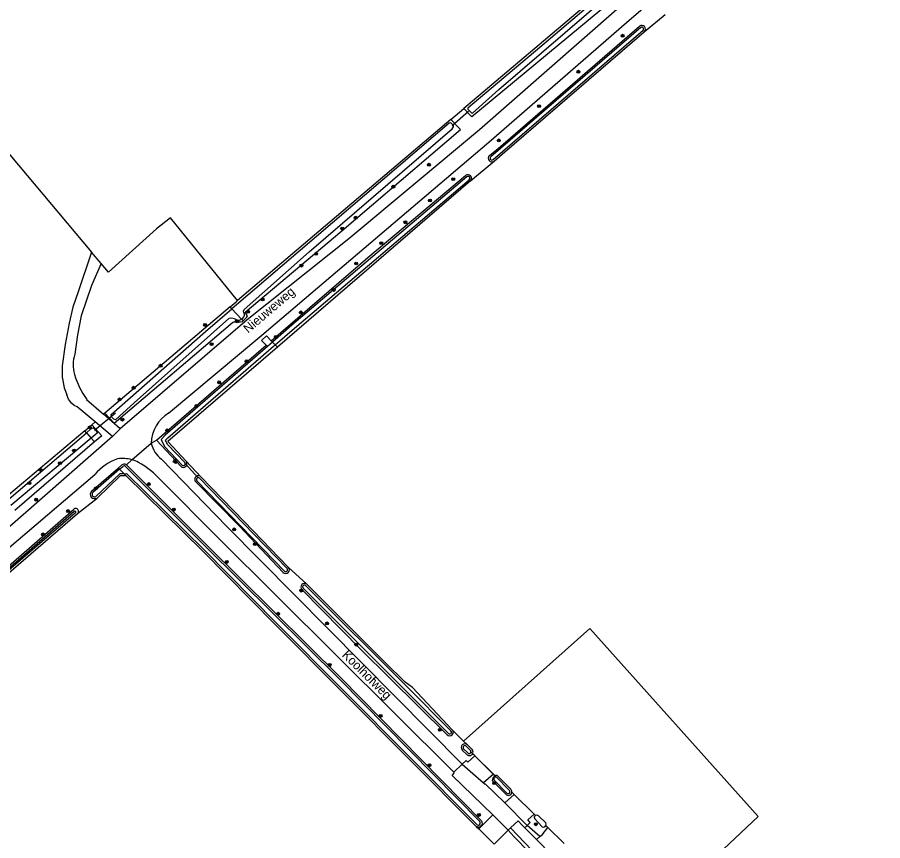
# Model space of a CAD drawing. Extents: x 141000 to 143000, y 400580 to 403500.
# Drawn here: x 142087.7 to 142326.5, y 403003.4 to 403230.8 of the extents above; entities that cross this region are included whole.
import ezdxf

# ---------------------------------------------------------------- set-up
doc = ezdxf.new("R2010")
doc.units = 0
for name, color, linetype in [('gg-anno-openbare ruimte label', 7, 'Continuous'), ('gg-knt-bronhoudergrens', 7, 'Continuous'), ('gg-knt-onverhard', 7, 'Continuous'), ('gg-knt-verharding', 7, 'Continuous'), ('gg-knt-verharding nz', 7, 'Continuous'), ('gg-kntw-bovenkant insteek waterloop', 7, 'Continuous'), ('gg-kntw-waterlijn', 7, 'Continuous'), ('gg-kwrk-duiker nz buis', 7, 'Continuous'), ('gt-grn-groengrens', 7, 'Continuous'), ('gt-grn-vlakafsluiter', 7, 'Continuous'), ('gt-grn-weggrens', 7, 'Continuous'), ('gt-symb-boom', 7, 'Continuous'), ('gt-symb-brandkraan', 7, 'Continuous'), ('gt-symb-waterafsluiter', 7, 'Continuous')]:
    doc.layers.add(name, color=color, linetype=linetype)

# ---------------------------------------------------------------- blocks, each defined once
blk = doc.blocks.new('gt0-BOOM')
at = {"layer": 'gt-symb-boom'}
for radius in [0.4, 0.2]:
    blk.add_circle((0, 0), radius, dxfattribs=at)
blk = doc.blocks.new('gt0-WAFSL')
at = {"layer": 'gt-symb-waterafsluiter'}
for p, q in [((-0.5, -0.33), (0, 0.67)), ((0, 0.67), (0.5, -0.33)), ((0.5, -0.33), (-0.5, -0.33))]:
    blk.add_line(p, q, dxfattribs=at)
blk = doc.blocks.new('gt0-BR')
at = {"layer": 'gt-symb-brandkraan'}
for centre, radius, start, end in [((-0.24, 0), 0.206, 107.5669, 252.4331), ((0.6, -2.66), 3, 106.892, 107.5669), ((0, -0.69), 0.938, 73.108, 106.892), ((-0.6, -2.66), 3, 72.4331, 73.108), ((0.24, 0), 0.206, 287.567, 72.4331), ((0.6, 2.66), 3, 252.4331, 253.108), ((0, 0.69), 0.938, 253.108, 286.8921), ((-0.6, 2.66), 3, 286.8921, 287.567)]:
    blk.add_arc(centre, radius, start, end, dxfattribs=at)

msp = doc.modelspace()

# ---------------------------------------------------------------- linework, layer by layer
at = {"layer": 'gg-knt-bronhoudergrens'}
for p, q in [((142260.7, 403226.8), (142266.52, 403231.53)), ((142207.31, 403202.55), (142210.95, 403205.59)), ((142212.74, 403185.58), (142219.29, 403191.07)), ((142138.33, 403103.86), (142134.23, 403108.17)), ((142104.32, 403093.73), (142109.68, 403098.03)), ((142167.55, 403074.21), (142162.46, 403078.9)), ((142207.71, 403034.05), (142210.84, 403030.92)), ((142210.84, 403030.92), (142211.88, 403029.88)), ((142214.35, 403007.34), (142215.06, 403006.63)), ((142215.06, 403006.63), (142219.28, 403002.43))]:
    msp.add_line(p, q, dxfattribs=at)
for points in [[(142018.46, 403199.94), (142054.28, 403230.01), (142108.17, 403165.95)], [(142148.46, 403152.56), (142129.93, 403175.44), (142126.09, 403172.32), (142112.85, 403160.38), (142110.82, 403162.8)], [(142210.84, 403030.92), (142245.72, 403061.99), (142292.19, 403010.09), (142261.85, 402981.56)]]:
    msp.add_lwpolyline(points, dxfattribs=at)
at = {"layer": 'gg-knt-onverhard'}
for p, q in [((142110.82, 403162.8), (142108.17, 403165.95)), ((142218.91, 403010.5), (142215.06, 403006.63)), ((142223.1, 403006.27), (142219.28, 403002.43))]:
    msp.add_line(p, q, dxfattribs=at)
for points in [[(142210.49, 403024.54), (142145.47, 403090.13), (142127.46, 403108.75)], [(142127.35, 403102.83), (142143.07, 403087.03), (142208.11, 403022.33)]]:
    msp.add_lwpolyline(points, dxfattribs=at)
for centre, radius, start, end in [((142132.29, 403114.98), 7.88, 193.4484, 232.2377), ((142116.75, 403099.86), 9.1, 61.3827, 73.9104), ((142110.3, 403087.98), 22.61, 41.0533, 61.4369)]:
    msp.add_arc(centre, radius, start, end, dxfattribs=at)
at = {"layer": 'gg-knt-verharding'}
for p, q in [((142116.02, 403117.12), (142113.94, 403114.98)), ((142208.11, 403022.33), (142210.49, 403024.54)), ((142219.09, 403021.77), (142216.3, 403019.41)), ((142222.18, 403013.9), (142224.78, 403016.19)), ((142231.92, 403004.57), (142228.4, 403007.62)), ((142223.78, 403006.91), (142229.69, 403000.79)), ((142230.98, 403003.74), (142227.74, 403006.96)), ((142235.23, 402999.43), (142230.98, 403003.74))]:
    msp.add_line(p, q, dxfattribs=at)
for points in [[(142129.43, 403121.45), (142155.13, 403142.95), (142217.83, 403196.26), (142255.83, 403229.33), (142298.44, 403265.98), (142313.46, 403277.45), (142353.81, 403312.2), (142392, 403344.92)], [(142362.71, 403326.12), (142350.92, 403316.23), (142295.63, 403269.59), (142253.14, 403232.93), (142215.27, 403199.68), (142179.13, 403169.58), (142151.11, 403147.23), (142116.02, 403117.12)], [(142113.94, 403114.98), (142069.01, 403075.7), (142040.23, 403051.3), (141996.37, 403014.63), (141979.56, 403000.04), (141957.73, 402981.47)], [(141914.25, 402939.09), (141985.78, 403000), (142000, 403012.42), (142042.58, 403048.33), (142071.63, 403072.64), (142109.08, 403104.56)], [(142210.49, 403024.54), (142211.58, 403025.55), (142212.04, 403025.1), (142213.94, 403026.8)], [(142218.91, 403010.5), (142207.69, 403021.43), (142208.23, 403022.04), (142208.04, 403022.27), (142208.11, 403022.33)], [(142216.3, 403019.41), (142216.78, 403019.01), (142216.84, 403019.08), (142222.18, 403013.9)], [(142223.1, 403006.27), (142222.3, 403007.12), (142218.91, 403010.5)], [(142228.4, 403007.62), (142229.21, 403008.44), (142228.56, 403009.14), (142230.36, 403010.72)], [(142223.78, 403006.91), (142225.94, 403008.92), (142226.93, 403007.77), (142227.74, 403006.96)], [(142229.05, 403000.17), (142224.8, 403004.45), (142223.1, 403006.27)], [(142231.92, 403004.57), (142232.49, 403005.02), (142234.12, 403007.04)]]:
    msp.add_lwpolyline(points, dxfattribs=at)
for centre, radius, start, end in [((142134.5, 403112.97), 9.88, 120.8938, 178.951), ((142119.97, 403095.36), 14.25, 108.9408, 139.789), ((142116.76, 403099.86), 9.09, 73.9261, 98.9757)]:
    msp.add_arc(centre, radius, start, end, dxfattribs=at)
at = {"layer": 'gg-knt-verharding nz'}
for p, q in [((142228.4, 403007.62), (142227.74, 403006.96)), ((142223.78, 403006.91), (142223.1, 403006.27)), ((142230.98, 403003.74), (142231.92, 403004.57))]:
    msp.add_line(p, q, dxfattribs=at)
at = {"layer": 'gg-kntw-bovenkant insteek waterloop'}
for p, q in [((142277.23, 403261.71), (142210.95, 403205.59)), ((142207.31, 403202.55), (142148.46, 403152.56)), ((142212.74, 403185.58), (142159.44, 403139.68)), ((142146.4, 403150.81), (142111.85, 403121.47)), ((142126.07, 403114.03), (142156.38, 403140.22)), ((142106.28, 403116.6), (142108.24, 403118.26)), ((142109.01, 403113.52), (142086.98, 403094.57)), ((142132.78, 403106.79), (142126.07, 403114.03)), ((142108.17, 403099.91), (142115.55, 403106.3)), ((142115.55, 403106.3), (142116.45, 403107.08)), ((142211.88, 403029.88), (142213.35, 403028.38)), ((142211.8, 403027.11), (142210.49, 403028.44)), ((142222.46, 403016.21), (142218.76, 403019.99)), ((142219.44, 403021.3), (142219.52, 403021.34)), ((142220.04, 403021.54), (142223.05, 403018.45)), ((142223.05, 403018.45), (142223.86, 403017.64)), ((142231.53, 403010.31), (142231.36, 403010.38)), ((142233.58, 403008.29), (142231.53, 403010.31)), ((142230.47, 403009.41), (142232.55, 403007.26))]:
    msp.add_line(p, q, dxfattribs=at)
for points in [[(142301.84, 403277.83), (142294.39, 403271.48), (142251.65, 403235.24), (142213.15, 403203.31), (142210.95, 403205.59)], [(142218, 403192.6), (142220.38, 403194.56), (142259.39, 403228.31)], [(142219.29, 403191.07), (142221.49, 403193), (142260.7, 403226.8)], [(142149.98, 403146.97), (142150.18, 403147.15), (142150.94, 403147.92), (142151.2, 403148.37), (142150.56, 403149.33), (142177.23, 403171.8), (142210, 403199.83), (142207.31, 403202.55)], [(142157.77, 403141.4), (142184.45, 403164.44), (142211.41, 403187.07)], [(142146.4, 403150.81), (142148.05, 403152.21), (142148.46, 403152.56)], [(142111.85, 403121.47), (142114.37, 403118.71), (142147.07, 403146.52), (142147.42, 403146.64), (142148.6, 403146.72), (142149.18, 403146.68), (142149.78, 403146.8), (142149.98, 403146.97)], [(142156.38, 403140.22), (142155.03, 403141.5), (142156.48, 403142.84), (142157.77, 403141.4)], [(142159.44, 403139.68), (142129.21, 403113.65), (142134.23, 403108.17)], [(142108.24, 403118.26), (142110.97, 403115.21), (142109.01, 403113.52)], [(142106.28, 403116.6), (142085.31, 403098.86), (142085.19, 403098.75), (142084.18, 403097.9)], [(142117.81, 403107.19), (142140.08, 403084.87), (142176.97, 403048.39), (142215.78, 403008.92), (142215.9, 403008.57), (142215.96, 403007.9), (142215.55, 403007.42), (142215.1, 403007.02), (142214.35, 403007.34)], [(142109.68, 403098.03), (142116.14, 403104.24), (142117.63, 403104.26)], [(142117.63, 403104.26), (142138.85, 403083.33), (142158.85, 403063.08), (142214.35, 403007.34)], [(142162.46, 403078.9), (142150.26, 403091.54), (142138.33, 403103.86)], [(142161.03, 403077.5), (142148.95, 403090.22), (142136.9, 403102.47)], [(142002.23, 403008.95), (142005.78, 403011.79), (142027.06, 403029.52), (142066.63, 403063.32), (142070.81, 403066.65), (142103.18, 403094.88)], [(142003.62, 403007.33), (142007.25, 403010.28), (142028.05, 403028.17), (142067.65, 403062.22), (142071.61, 403065.62), (142104.32, 403093.73)], [(142206.29, 403032.64), (142182.54, 403056.09), (142166.2, 403072.74)], [(142207.71, 403034.05), (142196.71, 403045.73), (142194.72, 403047.21), (142189.15, 403052.7), (142167.55, 403074.21)], [(142219.52, 403021.34), (142219.73, 403021.45), (142220.04, 403021.54)]]:
    msp.add_lwpolyline(points, dxfattribs=at)
for centre, radius, start, end in [((142260.05, 403227.55), 1, 310.8159, 130.7532), ((142218.65, 403191.84), 1, 130.7754, 309.2026), ((142212.05, 403186.31), 1, 313.6011, 130.318), ((142133.5, 403107.49), 1, 224.1342, 42.9884), ((142117.19, 403106.38), 1.02, 52.3409, 136.8669), ((142137.62, 403103.16), 1, 44.1479, 224.1504), ((142109.03, 403099.05), 1.21, 135.0902, 302.5414), ((142103.75, 403094.31), 0.809, 314.3724, 134.3761), ((142161.75, 403078.2), 1, 224.1503, 44.148), ((142166.91, 403073.45), 1, 49.6731, 225.1122), ((142207, 403033.35), 1, 224.8575, 44.7779), ((142211.19, 403029.16), 1, 46.1765, 226.1733), ((142212.44, 403027.91), 1.03, 231.0576, 330.3978), ((142212.43, 403027.91), 1.03, 330.6858, 27.2033), ((142220.29, 403020.03), 1.52, 123.6435, 181.6306), ((142223.16, 403016.93), 0.998, 352.8578, 45.6064), ((142223.16, 403016.92), 1, 225.5504, 352.9573), ((142231.02, 403009.8), 0.672, 118.3061, 215.4148), ((142231.02, 403009.8), 0.669, 59.7529, 118.5004), ((142232.9, 403007.94), 0.767, 331.637, 27.5661), ((142232.9, 403007.94), 0.767, 242.8576, 331.7167)]:
    msp.add_arc(centre, radius, start, end, dxfattribs=at)
at = {"layer": 'gg-kntw-waterlijn'}
for p, q in [((142259.72, 403227.93), (142218.33, 403192.22)), ((142218.98, 403191.47), (142260.37, 403227.18)), ((142158.1, 403141.03), (142157.77, 403141.4)), ((142156.76, 403139.86), (142156.38, 403140.22)), ((142108.07, 403114.58), (142085.84, 403095.93)), ((142115.91, 403105.95), (142108.52, 403099.54)), ((142137.97, 403103.51), (142162.11, 403078.55)), ((142137.26, 403102.81), (142161.39, 403077.85)), ((142212.84, 403028.19), (142211.53, 403029.52)), ((142210.84, 403028.8), (142211.98, 403027.64)), ((142219.14, 403020.32), (142222.81, 403016.57)), ((142219.71, 403021.04), (142219.81, 403021.07)), ((142223.52, 403017.28), (142219.81, 403021.07))]:
    msp.add_line(p, q, dxfattribs=at)
for points in [[(142299.84, 403279.96), (142267.53, 403252.81), (142253.13, 403240.58), (142231.91, 403222.4), (142212.03, 403205.71), (142212.03, 403205.43), (142213.01, 403204.36), (142213.3, 403204.34), (142220.58, 403210.83), (142250.63, 403236.79), (142298.87, 403277.42), (142300.74, 403279)], [(142149.58, 403147.41), (142149.94, 403147.69), (142150.22, 403148.07), (142150.37, 403148.54), (142150.33, 403148.82), (142150.17, 403149.22), (142150.07, 403149.66), (142150.32, 403150.1), (142168.19, 403166.04), (142207.67, 403199.98), (142208.08, 403200.49), (142208.06, 403200.85), (142207.29, 403201.67), (142206.88, 403201.54), (142146.91, 403150.26)], [(142211.73, 403186.69), (142163.48, 403145.72), (142158.1, 403141.03)], [(142158.81, 403140.32), (142164.13, 403144.96), (142212.38, 403185.92)], [(142149.58, 403147.41), (142149.42, 403147.28), (142148.92, 403147.09), (142148.38, 403147.16), (142147.64, 403147.48), (142146.74, 403147.65), (142146.07, 403147.57), (142119.91, 403124.34), (142114.77, 403119.61), (142114.3, 403119.82), (142113.71, 403120.46), (142113.57, 403121.08), (142139.57, 403143.98), (142146.91, 403150.26)], [(142156.76, 403139.86), (142128.5, 403115.36), (142127.41, 403114.17), (142128.32, 403112.21), (142133.14, 403107.14)], [(142133.86, 403107.84), (142129.16, 403112.79), (142128.6, 403113.99), (142129.2, 403114.64), (142158.38, 403139.95), (142158.81, 403140.32)], [(142084.73, 403097.25), (142084.78, 403097.29), (142104.76, 403114.31), (142106.75, 403116.07)], [(142106.75, 403116.07), (142107.88, 403117.07), (142108.53, 403117.39), (142109.08, 403117.17), (142109.73, 403116.13), (142109.7, 403115.95), (142108.07, 403114.58)], [(142115.91, 403105.95), (142116.79, 403106.72), (142116.81, 403106.74)], [(142117.13, 403104.75), (142117.83, 403104.76), (142139.2, 403083.68), (142159.2, 403063.43), (142214.63, 403007.76), (142215.01, 403007.6), (142215.19, 403007.77), (142215.44, 403008.07), (142215.4, 403008.46), (142215.34, 403008.66), (142176.62, 403048.04), (142139.73, 403084.52), (142117.48, 403106.81)], [(142117.13, 403104.75), (142115.94, 403104.74), (142109.38, 403098.43)], [(142103.33, 403094.3), (142071.13, 403066.27), (142066.95, 403062.93), (142027.34, 403029.19), (142002.8, 403008.76)], [(142103.77, 403093.92), (142071.28, 403066), (142067.33, 403062.6), (142027.66, 403028.61), (142003.39, 403008.02)], [(142166.55, 403073.09), (142194.37, 403045.36), (142206.64, 403033)], [(142167.26, 403073.8), (142195.07, 403046.06), (142207.35, 403033.7)], [(142212.86, 403027.89), (142212.87, 403028.04), (142212.84, 403028.19)]]:
    msp.add_lwpolyline(points, dxfattribs=at)
for centre, radius, start, end in [((142260.05, 403227.55), 0.5, 310.7694, 130.7937), ((142218.65, 403191.85), 0.501, 130.8499, 310.7251), ((142212.05, 403186.31), 0.5, 310.2662, 130.4018), ((142117.19, 403106.38), 0.519, 55.3103, 136.8847), ((142133.5, 403107.49), 0.5, 224.1917, 44.1876), ((142137.62, 403103.16), 0.5, 44.1871, 224.1922), ((142109.03, 403099.05), 0.712, 136.3774, 299.0228), ((142103.55, 403094.11), 0.294, 319.04, 139.1017), ((142161.75, 403078.2), 0.5, 224.1528, 44.1466), ((142166.91, 403073.45), 0.5, 45.0001, 225.162), ((142207, 403033.35), 0.5, 224.7546, 44.7592), ((142211.19, 403029.16), 0.5, 46.2186, 226.2122), ((142212.36, 403027.99), 0.518, 223.6504, 348), ((142220.02, 403020.21), 0.882, 110.4683, 173.0134), ((142223.16, 403016.92), 0.5, 224.9176, 44.9203)]:
    msp.add_arc(centre, radius, start, end, dxfattribs=at)
at = {"layer": 'gg-kwrk-duiker nz buis'}
for p, q in [((142212.23, 403204.76), (142207.67, 403200.83)), ((142108.93, 403116.76), (142114.77, 403121.59)), ((142134.05, 403107.42), (142137.51, 403103.69)), ((142212.82, 403027.93), (142219.71, 403021.04))]:
    msp.add_line(p, q, dxfattribs=at)
at = {"layer": 'gt-grn-groengrens'}
for p, q in [((142106.81, 403125.23), (142111.44, 403121.15)), ((142111.85, 403121.47), (142111.44, 403121.15)), ((142116.02, 403117.12), (142111.44, 403121.15)), ((142109.12, 403119.03), (142108.24, 403118.26)), ((142113.94, 403114.98), (142109.12, 403119.03)), ((142124.62, 403113.15), (142126.07, 403114.03)), ((142119.27, 403108.6), (142117.81, 403107.19)), ((142224.78, 403016.19), (142224.15, 403016.8)), ((142230.36, 403010.72), (142230.7, 403010.39)), ((142234.12, 403007.04), (142233.57, 403007.58))]:
    msp.add_line(p, q, dxfattribs=at)
for points in [[(142108.17, 403165.95), (142104.43, 403154.97), (142103.02, 403150.69), (142101.95, 403146.32), (142100.87, 403140.43), (142100.06, 403134.49)], [(142110.82, 403162.8), (142108.19, 403156.75), (142105.3, 403148.33), (142104.3, 403143.05), (142103.52, 403137.74)], [(142109.12, 403119.03), (142104.2, 403123.17), (142103.33, 403123.58), (142102.61, 403124.21), (142101.84, 403125.31), (142101.3, 403126.54)]]:
    msp.add_lwpolyline(points, dxfattribs=at)
for centre, radius, start, end in [((142112.34, 403134.85), 9.28, 161.8738, 196.8737), ((142117.45, 403133.13), 17.45, 175.5416, 202.2052), ((142126.33, 403138.94), 23.85, 196.5126, 215.0792)]:
    msp.add_arc(centre, radius, start, end, dxfattribs=at)
at = {"layer": 'gt-grn-vlakafsluiter'}
for p, q in [((142146.91, 403150.26), (142146.4, 403150.81)), ((142149.58, 403147.41), (142146.91, 403150.26)), ((142149.98, 403146.97), (142149.58, 403147.41)), ((142158.81, 403140.32), (142158.1, 403141.03)), ((142158.81, 403140.32), (142159.44, 403139.68)), ((142106.75, 403116.07), (142106.28, 403116.6)), ((142106.75, 403116.07), (142108.07, 403114.58)), ((142108.07, 403114.58), (142109.01, 403113.52)), ((142115.91, 403105.95), (142115.55, 403106.3)), ((142117.13, 403104.75), (142115.91, 403105.95)), ((142117.13, 403104.75), (142117.63, 403104.26)), ((142213.94, 403026.8), (142213.33, 403027.4)), ((142219.09, 403021.77), (142213.94, 403026.8)), ((142210.49, 403024.54), (142216.3, 403019.41)), ((142219.09, 403021.77), (142219.52, 403021.34)), ((142230.36, 403010.72), (142224.78, 403016.19)), ((142222.18, 403013.9), (142228.4, 403007.62)), ((142238.61, 403002.64), (142234.12, 403007.04))]:
    msp.add_line(p, q, dxfattribs=at)
msp.add_lwpolyline([(142158.1, 403141.03), (142157.4, 403140.42), (142156.76, 403139.86)], dxfattribs=at)
at = {"layer": 'gt-grn-weggrens'}
msp.add_line((142119.27, 403108.6), (142124.62, 403113.15), dxfattribs=at)

# ---------------------------------------------------------------- block references
at = {"layer": 'gt-symb-boom'}
for p in [(142254.74, 403225.68), (142242.52, 403215.75), (142231.68, 403206.23), (142220.56, 403196.77), (142201.28, 403190.05), (142191.45, 403183.98), (142207.99, 403186.07), (142201.55, 403180.17), (142181.06, 403175.43), (142177.35, 403172.43), (142194.77, 403174.16), (142188.11, 403168.4), (142170.14, 403165.49), (142181.2, 403162.78), (142166.09, 403162.21), (142175.02, 403155.49), (142155.37, 403152.86), (142151.38, 403149.45), (142165.92, 403149.27), (142139.5, 403145.83), (142148.33, 403146.82), (142159.05, 403142.5), (142141.28, 403140.52), (142127.21, 403134.56), (142150.96, 403135.77), (142143.37, 403129.97), (142119.76, 403128.47), (142115.86, 403125.25), (142137.12, 403123.44), (142116.67, 403119.69), (142107.65, 403117.52), (142129.03, 403116.7), (142103.32, 403111.15), (142099.42, 403107.65), (142094.11, 403105.78), (142091.01, 403102.16), (142109.39, 403100.75), (142123.96, 403101.88), (142092.87, 403097.57), (142101.67, 403094.41), (142130.87, 403094.82), (142147.52, 403089.37), (142094.78, 403087.98), (142153.23, 403085.29), (142145.49, 403080.39), (142166.03, 403072.46), (142159.67, 403066.06), (142173.17, 403063.39), (142181.22, 403057.54), (142173.85, 403051.92), (142187.93, 403037.86), (142204.33, 403034), (142201.39, 403024.26), (142219.27, 403019.29), (142215.08, 403010.52), (142230.79, 403007.94)]:
    msp.add_blockref('gt0-BOOM', p, dxfattribs=at)
at = {"layer": 'gt-symb-brandkraan'}
msp.add_blockref('gt0-BR', (142131.41, 403107.94), dxfattribs=at)
at = {"layer": 'gt-symb-waterafsluiter'}
msp.add_blockref('gt0-WAFSL', (142131.18, 403108.28), dxfattribs=at)

# ---------------------------------------------------------------- texts
at = {"layer": 'gg-anno-openbare ruimte label'}
for s, rotation, p in [('Nieuweweg', 40.4, (142151.37, 403143.41)), ('Koolhofweg', 315.2, (142177.1, 403054.48))]:
    msp.add_text(s, height=2.5, rotation=rotation, dxfattribs=at).set_placement(p)

doc.saveas('drawing.dxf')
